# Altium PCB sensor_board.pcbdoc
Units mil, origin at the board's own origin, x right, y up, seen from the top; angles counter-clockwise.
Board outline 4167.27 x 3144 mil, 2 copper layers (Top Layer, Bottom Layer); 44 components, 32 nets, 169 pads, 59 vias.
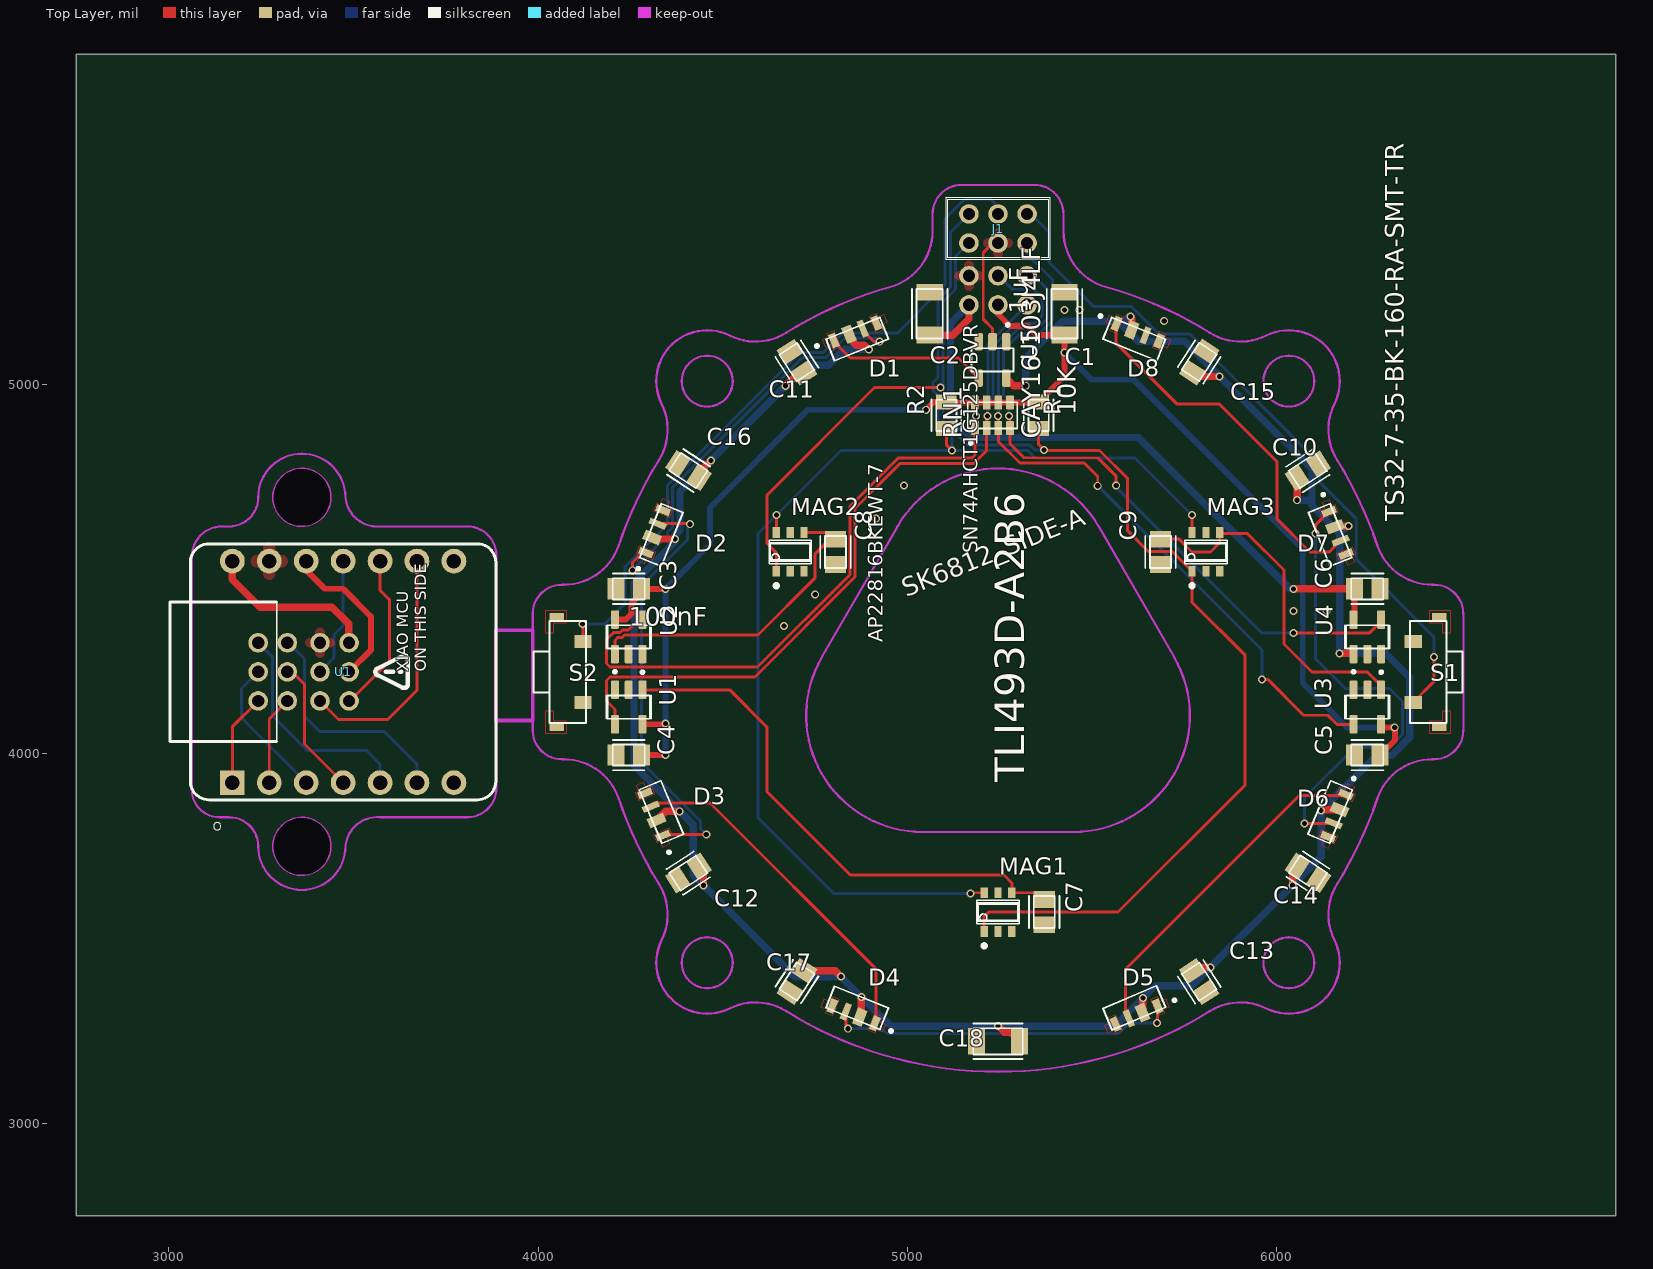
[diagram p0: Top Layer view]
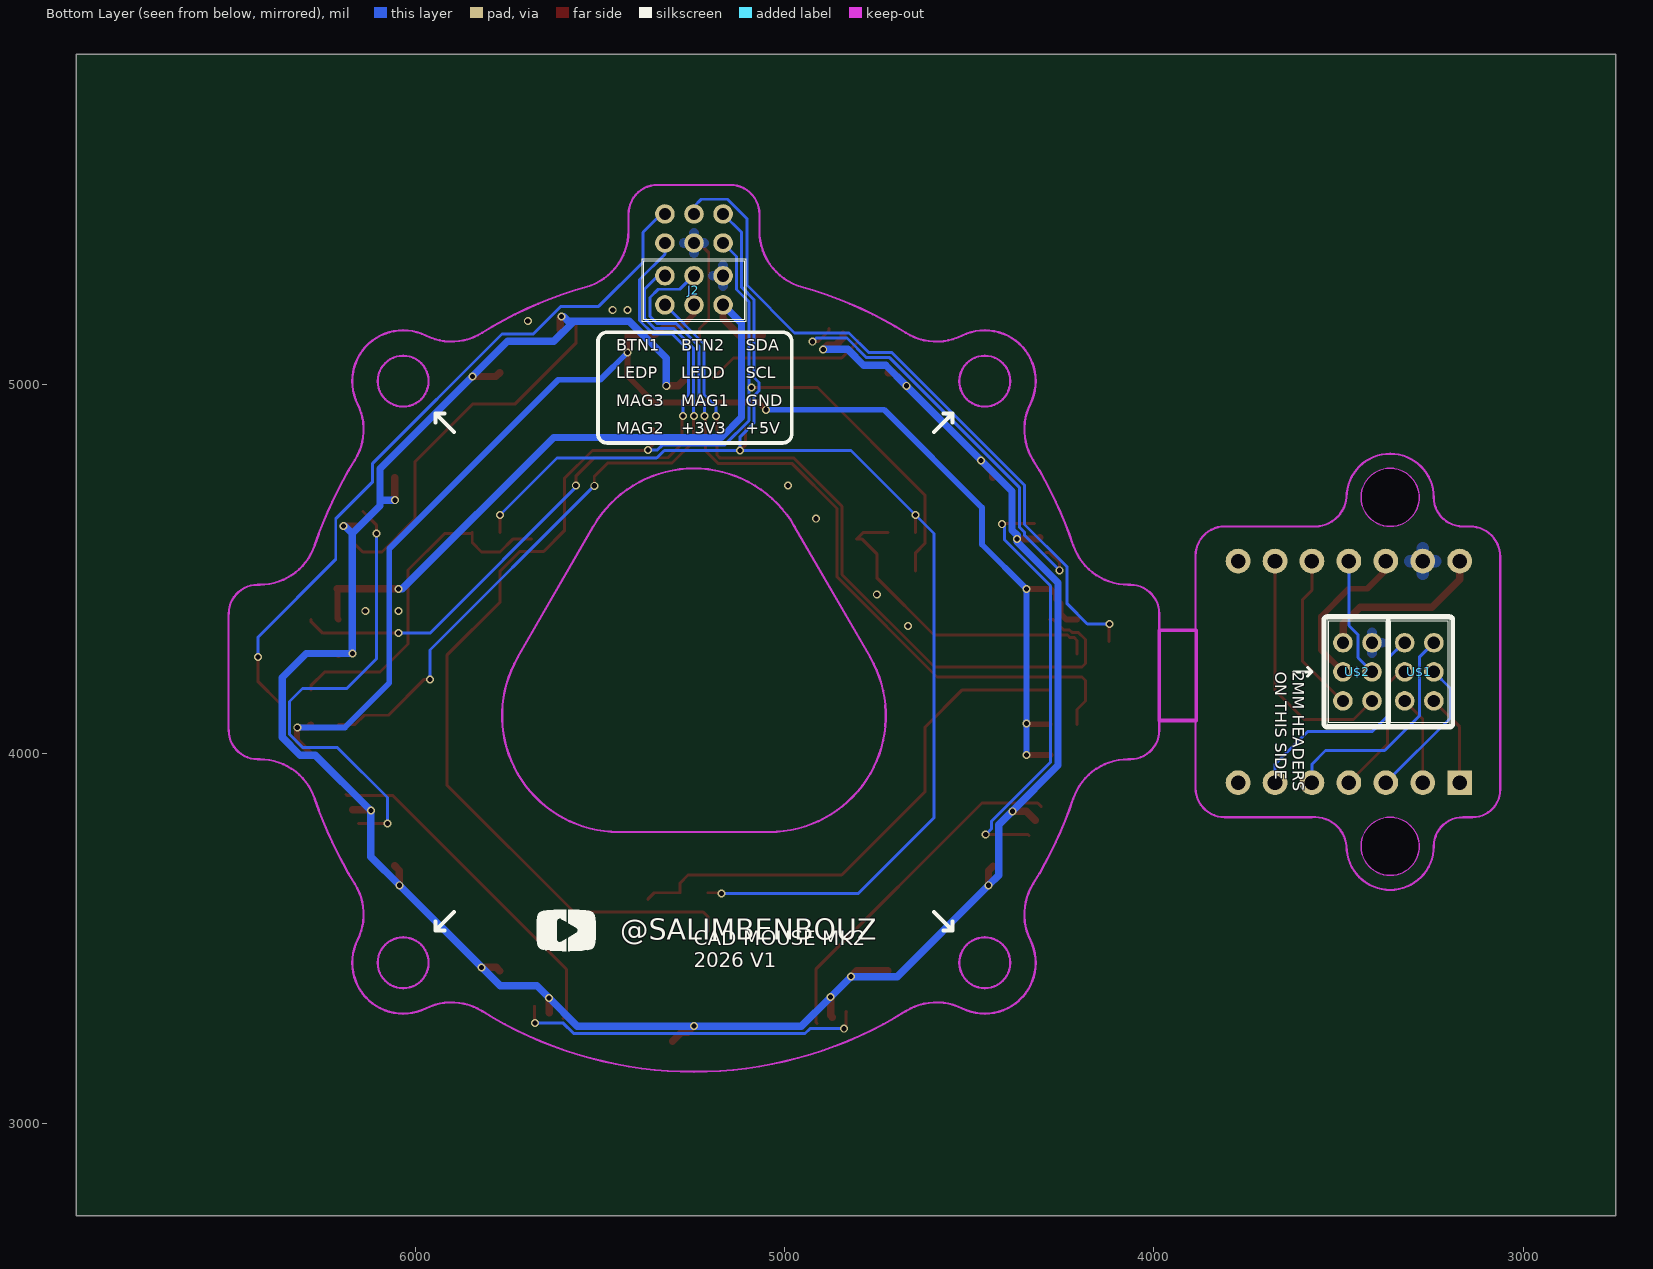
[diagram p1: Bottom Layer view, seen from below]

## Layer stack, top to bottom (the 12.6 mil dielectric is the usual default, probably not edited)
Top Layer: signal copper (thickness not stored)
Dielectric: dielectric 12.6, FR-4, Dk 4.8
Bottom Layer: signal copper (thickness not stored)

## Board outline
6917.27,2750 2750,2750 2750,5894 6917.27,5894
cut-out: 3438.93,3749.95 cw(c3360.19,3749.95) 3281.45,3749.95 cw(c3360.19,3749.95)
cut-out: 3438.93,4694.83 cw(c3360.19,4694.83) 3281.45,4694.83 cw(c3360.19,4694.83)

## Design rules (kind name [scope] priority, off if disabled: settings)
BoardOutlineClearance safeClearance [All] p0: genericclearance=10 ignorepadtopadclearanceinfootprint=FALSE except(0: SMDPad-CutoutEdge THPad-CutoutEdge Via-CutoutEdge Fill-CutoutEdge Arc-SplitContinuation Track-SplitContinuation SMDPad-SplitContinuation THPad-SplitContinuation Via-SplitContinuation Fill-SplitContinuation Poly-SplitContinuation Region-SplitContinuation Text-SplitContinuation; 6: Track-CutoutEdge; 10: Region-CutoutEdge; 11.8: Track-OutlineEdge SMDPad-OutlineEdge THPad-OutlineEdge Via-OutlineEdge Fill-OutlineEdge Region-OutlineEdge Poly-OutlineEdge Text-OutlineEdge)
Clearance safeClearance [(InNet('GND') OR InNet('N$1') OR InNet('N$2') OR InNet('N$4') OR InNet('N$5') OR InNet('N$6') OR InNet('G_5V') OR InNet('5V') OR InNet('SCL') OR InNet('SDA') OR InNet('G_MAG1') OR InNet('G_MAG2') OR InNet('G_MAG3') OR InNet('3V3') OR InNet('BTN_1') OR InNet('BTN_2') OR InNet('LED_DIN') OR InNet('N$3') OR InNet('N$7') OR InNet('~EN_MAG2~') OR InNet('D3') OR InNet('D0') OR InNet('D1') OR InNet('D8') OR InNet('D9') OR InNet('D2') OR InNet('D10') OR InNet('SDA1') OR InNet('SCL1') OR InNet('3V31') OR InNet('5V1') OR InNet('GND1'))] p1: gap=7 ignorepadtopadclearanceinfootprint=FALSE except(0: SMDPad-THPad THPad-THPad THPad-Via SMDPad-Fill THPad-Fill Via-Fill Fill-Fill SMDPad-Region THPad-Region Via-Region Fill-Region SMDPad-Poly THPad-Poly Via-Poly Fill-Poly Region-Poly Poly-Poly SMDPad-Text THPad-Text Via-Text Fill-Text Region-Text Poly-Text Text-Text SMDPad-Hole THPad-Hole Via-Hole Fill-Hole Region-Hole Poly-Hole Text-Hole; 6: Track-Track Track-SMDPad SMDPad-SMDPad Track-THPad Track-Via SMDPad-Via Via-Via Track-Fill Track-Region Track-Poly Track-Text Track-Hole; 10: Region-Region; 11.8: Track-Sheet SMDPad-Sheet THPad-Sheet Via-Sheet Fill-Sheet Region-Sheet Poly-Sheet Text-Sheet Sheet-Hole)
DiffPairsRouting differentialPair [All] p1: maxuncoupledlength=10 minlimit=6 maxlimit=6 mostfreqgap=6 toplayer_minwidth=5 toplayer_prefwidth=10 toplayer_maxwidth=100 bottomlayer_minwidth=5 bottomlayer_prefwidth=10 bottomlayer_maxwidth=100
PasteMaskExpansion Common [All] p1: expansion=0
PlaneConnect innerPlane [All] p1: planeconnectstyle=Relief reliefexpansion=20 reliefentries=4 reliefconductorwidth=10 reliefairgap=10
PolygonConnect CopperRegion [All] p1: connectstyle=Direct reliefentries=4 reliefconductorwidth=10 polygonreliefangle="90 Angle" airgapwidth=50
PolygonConnect CopperRegion1 [All] p1: connectstyle=Direct reliefentries=4 reliefconductorwidth=10 polygonreliefangle="90 Angle" airgapwidth=50
RoutingVias viaSize [All] p1: viastyle="Through Hole" holewidth=11.811 minholewidth=11.811 maxholewidth=78.7402 width=11.811 minwidth=11.811 maxwidth=102.3622
RoutingVias default [All] p1: viastyle="Through Hole" holewidth=0 minholewidth=0 maxholewidth=78.7402 width=0 minwidth=0 maxwidth=102.3622
SolderMaskExpansion Common [All] p1: useseparateexpansions=TRUE expansion=0 expansionbottom=0
Width trackWidth [All] p1: maxlimit=100 minlimit=6 preferedwidth=6
Width default [All] p1: maxlimit=100 minlimit=0 preferedwidth=0

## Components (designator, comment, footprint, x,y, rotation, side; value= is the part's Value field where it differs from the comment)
C1 "1uF" CAPC3216X135 5425.27,5192 r270 top
C2 "1uF" CAPC3216X135 5060.27,5192 r270 top
C3 "100nF" CAPC2012X110 4245.27,4447 r0 top
C4 "100nF" CAPC2012X110 4245.27,3997 r0 top
C5 "100nF" CAPC2012X110 6245.27,3997 r0 top
C6 "100nF" CAPC2012X110 6245.27,4447 r180 top
C7 "100nF" CAPC2012X110 5370.27,3572 r90 top
C8 "100nF" CAPC2012X110 4805.27,4547 r90 top
C9 "100nF" CAPC2012X110 5685.27,4547 r90 top
C10 "100nF" CAPC2012X110 6083.94,4766.64 r213 top
C11 "100nF" CAPC2012X110 4700.63,5060.67 r303 top
C12 "100nF" CAPC2012X110 4406.6,3677.36 r33 top
C13 "100nF" CAPC2012X110 5789.91,3383.33 r123 top
C14 "100nF" CAPC2012X110 6084.36,3678.25 r147 top
C15 "100nF" CAPC2012X110 5790.33,5061.55 r237 top
C16 "100nF" CAPC2012X110 4407.02,4767.52 r327 top
C17 "100nF" CAPC2012X110 4701.05,3384.21 r57 top
C18 "22uF" CAPC3216X135 5245.27,3222 r0 top
D1 "SK6812_SIDE-A" LED_SK6812_SIDE-A 4864.03,5123.25 r22 top
D2 "SK6812_SIDE-A" LED_SK6812_SIDE-A 4333.66,4592.88 r68 top
D3 "SK6812_SIDE-A" LED_SK6812_SIDE-A 4333.66,3842.82 r113 top
D4 "SK6812_SIDE-A" LED_SK6812_SIDE-A 4864.03,3312.45 r158 top
D5 "SK6812_SIDE-A" LED_SK6812_SIDE-A 5614.09,3312.45 r203 top
D6 "SK6812_SIDE-A" LED_SK6812_SIDE-A 6144.46,3842.82 r247 top
D7 "SK6812_SIDE-A" LED_SK6812_SIDE-A 6144.46,4592.88 r292 top
D8 "SK6812_SIDE-A" LED_SK6812_SIDE-A 5614.09,5123.25 r338 top
J1 "NPPN032AFCN-RCCONN3X2_NPPN032AFCN-RC_SUL" CONN3X2_NPPN032AFCN-RC_SUL 5245.27,5422.79 r0 top
J2 "NPPN032AFCN-RCCONN3X2_NPPN032AFCN-RC_SUL" CONN3X2_NPPN032AFCN-RC_SUL 5245.27,5255.46 r0 bottom
MAG1 "TLI493D-A2B6" SOP95P280X110-6N-V 5245.27,3572 r90 top
MAG2 "TLI493D-A2B6" SOP95P280X110-6N-V 4682.35,4547 r90 top
MAG3 "TLI493D-A2B6" SOP95P280X110-6N-V 5808.19,4547 r90 top
R1 "10K" RESC2012X65 5355.27,4917 r90 top
R2 "10K" RESC2012X65 5105.27,4917 r90 top
RN1 "CAY16-103J4LF" RESCAF80P320X160X60-8N 5230.27,4917 r90 top
S1 "TS32-7-35-BK-160-RA-SMT-TR" SW_TS32-7-35-BK-160-RA-SMT-TR 6420.27,4222 r90 top
S2 "TS32-7-35-BK-160-RA-SMT-TR" SW_TS32-7-35-BK-160-RA-SMT-TR 4070.27,4222 r270 top
U1 "AP22816BKEWT-7" SOT95P280X100-5N 4245.27,4127 r270 top
U1 "XIAO-THRUHOLE" XIAO-GENERIC-THRUHOLE-MODULE14P-2.54-21X17.8MM 3472,4222.39 r90 top
U2 "AP22816BKEWT-7" SOT95P280X100-5N 4245.27,4317 r90 top
U3 "AP22816BKEWT-7" SOT95P280X100-5N 6245.27,4127 r270 top
U4 "AP22816BKEWT-7" SOT95P280X100-5N 6245.27,4317 r90 top
U5 "SN74AHCT1G125DBVR" SOT95P280X145-5N 5230.27,5067 r270 top
U$1 "NRPN032PAEN-RC" CONN3X2_NRPN032PAEN-RC 3281.45,4222.39 r90 bottom
U$2 "NRPN032PAEN-RC" CONN3X2_NRPN032PAEN-RC 3448.77,4222.39 r90 bottom

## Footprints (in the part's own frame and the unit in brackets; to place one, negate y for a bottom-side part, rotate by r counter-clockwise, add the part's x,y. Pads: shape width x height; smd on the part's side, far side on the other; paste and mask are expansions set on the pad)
CAPC2012X110 [mil]
  rect 45.85x57.69 smd: 1(-34.46,0) 2(34.46,0)
  silkscreen extent -43,-41 43,41
CAPC3216X135 [mil]
  rect 45.85x71.47 smd: 1(-58.09,0) 2(58.09,0)
  silkscreen extent -67,-48 67,48
CONN3X2_NPPN032AFCN-RC_SUL [mil]
  round 53 hole 33: 1(78.74,39.37) 2(78.74,-39.37) 3(0,39.37) 4(0,-39.37) 5(-78.74,39.37) 6(-78.74,-39.37)
  silkscreen extent -142,-84 142,84
CONN3X2_NRPN032PAEN-RC [mil]
  round 53 hole 33: 1(78.74,39.37) 2(78.74,-39.37) 3(0,39.37) 4(0,-39.37) 5(-78.74,39.37) 6(-78.74,-39.37)
  silkscreen extent -142,-84 142,84
LED_SK6812_SIDE-A [mm]
  rect 0.5x1 smd: 1(-1.525,0.525) 4(1.625,0.525)
  rect 0.7x1.2 smd: 2(-0.4,0.525)
  rect 0.45x1.2 smd: 3(0.625,0.525)
  silkscreen extent -2.85,-0.8 2,0.8
RESC2012X65 [mil]
  rect 40.6x55.91 smd: 1(-36.2,0) 2(36.2,0)
  silkscreen extent -42,-40 42,40
RESCAF80P320X160X60-8N [mm]
  rrect25% 0.97x0.53 smd: 1(-0.875,1.2) 2(-0.875,0.4) 3(-0.875,-0.4) 4(-0.875,-1.2) 5(0.875,-1.2) 6(0.875,-0.4) 7(0.875,0.4) 8(0.875,1.2)
  silkscreen extent -2,-1.7 0.9,1.7
SOP95P280X110-6N-V [mm]
  rect 0.75x0.5 smd: 1(-1.325,0.95) 2(-1.325,0) 3(-1.325,-0.95) 4(1.325,-0.95) 5(1.325,0) 6(1.325,0.95)
  silkscreen extent -2.45,-1.45 0.8,1.45
SOT95P280X100-5N [mm]
  rrect25% 1.26x0.55 smd: 1(-1.185,0.95) 2(-1.185,0) 3(-1.185,-0.95) 4(1.185,-0.95) 5(1.185,0.95)
  silkscreen extent -2.5,-1.55 0.8,1.55
SOT95P280X145-5N [mm]
  rrect50% 1.21x0.59 smd: 1(-1.255,0.95) 2(-1.255,0) 3(-1.255,-0.95) 4(1.255,-0.95) 5(1.255,0.95)
  silkscreen extent -2.51,-1.45 0.8,1.45
SW_TS32-7-35-BK-160-RA-SMT-TR [mm]
  rect 0.9x1.2 smd: 1(-2.1,1.3) 2(2.1,1.3)
  rect 0.5x1 smd: SH1(-3.8,-0.5) SH2(3.8,-0.5)
  silkscreen extent -3.5,-2.1 3.5,1.5
XIAO-GENERIC-THRUHOLE-MODULE14P-2.54-21X17.8MM [mm]
  rect 1.7x1.7 hole 1: 1(-7.62,7.62)
  round 1.7 hole 1: 2(-7.62,5.08) 3(-7.62,2.54) 4(-7.62,0) 5(-7.62,-2.54) 6(-7.62,-5.08) 7(-7.62,-7.62) 8(7.62,-7.62) 9(7.62,-5.08) 10(7.62,-2.54) 11(7.62,0) 12(7.62,2.54) 13(7.62,5.08) 14(7.62,7.62)
  silkscreen extent -10.87,-10.5 8.8,11.92

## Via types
v1: diameter 21.65, hole 13.78, Top Layer to Bottom Layer, 59 vias

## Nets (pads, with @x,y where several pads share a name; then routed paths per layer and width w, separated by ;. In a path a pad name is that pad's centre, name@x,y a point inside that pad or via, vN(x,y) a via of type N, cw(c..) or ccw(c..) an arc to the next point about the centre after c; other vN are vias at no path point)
3V3: C1.2 C3.2 C4.2 C5.2 J1.6 J2.3 J2.4 R1.2 R2.2 RN1.2 RN1.4 RN1.5 RN1.6 RN1.7 RN1.8 U1.4@4207.87,4080.35 U1.5@4282.67,4080.35 U2.5 U3.5 U4.4 | length 8244
  Top Layer w8: U1.4@4207.87,4080.35 4207.87,4120.47 4185.27,4143.07 4185.27,4199.24 4194.48,4208.46 4586.9,4208.46 4858.11,4479.67 4858.11,4664.84 4980.27,4787 5180.07,4787 5214.52,4821.45 RN1.2 5214.52,4913.29 v1(5216.76,4915.53) ; v1(5275.27,4915.53) 5277.51,4913.28 RN1.4 5277.51,4839.76 5315.27,4802 5515.27,4802 5565.27,4752 v1(5565.27,4727) ; v1(6045.27,4327) 6250.27,4327 6282.67,4359.4 U4.4
  Top Layer w15.98: R1.2 5425.27,5023.2 v1(5425.27,5087)
  Top Layer w16: U2.5 4236.47,4363.65 4252.84,4380.03 4252.84,4407.67 4264.73,4419.56 4264.73,4432 C3.2 v1(4345.27,4447) ; C4.2 v1(4345.27,3997) ; U1.5@4282.67,4080.35 4343.62,4080.35 v1(4345.27,4082) ; v1(5050.27,4932) 5071.47,4953.2 R2.2 5107.02,4951.45 RN1.8 RN1.7 RN1.6 RN1.5 5353.52,4951.45 R1.2 ; J2.3 5245.27,5191.09 5277.45,5158.91 5325.27,5158.91 5350.27,5133.91 C1.2 v1(5425.27,5087) ; C5.2 6320.27,4037.54 6320.27,4072 6291.02,4072 U3.5
  Bottom Layer w8: v1(5216.76,4915.53) 5216.76,4952.22 5232.27,4967.73 5232.27,5104.6 5293.26,5165.59 5344.93,5165.59 5364.51,5185.18 5364.51,5235.84 5342.01,5258.33 5283.89,5258.33 5247.39,5294.83 J2.4 ; v1(5275.27,4915.53) 5275.27,4957 5260.27,4972 5260.27,5093 5304.86,5137.59 5356.53,5137.59 5392.51,5173.58 5392.51,5284.76 5324.01,5353.26 5324.01,5383.42 ; v1(5565.27,4727) 5565.27,4722 5960.27,4327 v1(6045.27,4327)
  Bottom Layer w16: v1(4345.27,3997) v1(4345.27,4082) v1(4345.27,4447) 4465.27,4567 4465.27,4667 4730.27,4932 v1(5050.27,4932) ; v1(5425.27,5087) 5499.02,5013.25 5612.77,5013.25 6070.27,4555.75 6070.27,4192 6190.27,4072 v1(6319.44,4072)
3V31: U1.12 U$2.3 | length 426.2
  Top Layer w16: U1.12 3372,4497.39 3422,4447.39 3472,4447.39 3547,4372.39 3547,4281.25 U$2.3
5V: C2.2 C6.2 J2.5 U4.5 | length 1859.1
  Top Layer w16: U4.5 6210.8,4366.59 C6.2
  Top Layer w20: C2.2 5122.18,5133.91 5166.53,5178.26 J2.5 ; v1(6045.27,4447) C6.2
  Bottom Layer w20: J2.5 5116.53,5166.09 5116.53,4911.33 5170.86,4857 5625.27,4857 6035.27,4447 v1(6045.27,4447)
5V1: U1.14 U$2.1 | length 466.4
  Top Layer w20: U1.14 3172,4472.39 3247,4397.39 3442,4397.39 3487,4352.39 3487,4302.28 U$2.1
BTN_1: J1.5 S1.1 | length 1917.7
  Top Layer w8: S1.1 6425.27,4195.5 v1(6425.27,4262)
  Bottom Layer w8: 5324.01,5462.16 5334.01,5462.16 5383.62,5412.54 5383.62,5331.64 5503.26,5212 5605.27,5212 5680.27,5137 5765.27,5137 6115.27,4787 6115.27,4737 6215.27,4637 6215.27,4527 6425.27,4317 v1(6425.27,4262)
BTN_2: J1.3 S2.1 | length 1903.1
  Top Layer w8: v1(4120.27,4352) 4121.45,4350.82 S2.1
  Bottom Layer w8: v1(4120.27,4352) 4180.27,4352 4234.86,4406.59 4234.86,4506.04 4350.27,4621.45 4350.27,4727.76 4709.5,5087 4772.19,5087 4825.36,5140.17 4972.72,5140.17 5102.03,5269.48 5102.03,5449.28 5154.75,5502 5225.27,5502 5245.27,5482 J1.3
D0: U1.1@3172,3922.39 U$1.6 | length 250.3
  Top Layer w8: U1.1@3172,3922.39 3172,4073.57 U$1.6
D1: U1.2@3272,3922.39 U$1.5 | length 241.5
  Top Layer w8: U1.2@3272,3922.39 3272,4094.83 U$1.5
D2: U1.3@3372,3922.39 U$1.4 | length 391.1
  Bottom Layer w8: U$1.4@3242,4222.39 3197,4177.39 3197,4097.39 U1.3@3372,3922.39
D3: U1.4@3472,3922.39 U$1.3 | length 370.2
  Top Layer w8: U$1.3 3333.7,4222.39 3367.32,4188.77 3367.32,4027.07 U1.4@3472,3922.39
D8: U1.9 U$2.6 | length 666.1
  Top Layer w8: U$2.6 3459.66,4093.39 3593,4093.39 3672,4172.39 U1.9
D9: U1.10 U$2.5 | length 435.4
  Top Layer w8: U$2.5 3490.14,4143.65 3597,4250.51 3597,4418.39 3572,4443.39 U1.10
D10: U1.11 U$2.4 | length 325.9
  Bottom Layer w8: U$2.4 3447.64,4260.63 3447.64,4323.04 3472,4347.39 U1.11
G_5V: C10.2 C11.2 C12.2 C13.2 C14.2 C15.2 C16.2 C17.2 C18.2 D1.2 D2.2 D3.2 D4.2 D5.2 D6.2 D7.2 D8.2 U4.1 U5.5 | length 7558.9
  Top Layer w20: D2.2 4312.62,4582 v1(4370.27,4582) ; D3.2 4345.31,3844.77 v1(4383.04,3844.77) ; C12.2 4447.77,3683.87 v1(4447.77,3644.5) ; C16.2 4435.92,4762.65 v1(4467.77,4794.5) ; v1(4670.27,4997) 4705.03,5031.77 C11.2 ; C17.2 4804.15,3413.12 v1(4820.27,3397) ; D1.2 4841.69,5126.52 4861.21,5107 4883.62,5107 v1(4895.27,5095.35) ; D4.2 4875.27,3291.76 v1(4875.27,3342) ; v1(5245.27,3263.66) 5261.93,3247 5278.36,3247 C18.2 ; U5.5 5288.26,4997 v1(5320.27,4997) ; v1(5603.46,5184.36) 5607.23,5180.58 D8.2 ; D5.2 5636.66,3338.39 v1(5637.77,3339.5) ; C13.2 5780.9,3422 v1(5820.27,3422) ; C15.2 5782.21,5022 v1(5845.27,5022) ; v1(6042.77,3644.5) 6042.77,3684.33 C14.2 ; C10.2 6055.03,4687.23 v1(6055.27,4687) ; v1(6120.27,3847) 6122.51,3849.24 D6.2 ; D7.2 6159.5,4617 v1(6194.44,4617) ; v1(6170.27,4272) 6206.21,4272 U4.1
  Bottom Layer w20: v1(4383.04,3844.77) v1@4383.63,3845.36 ; v1(4895.27,5095.35) 4828.62,5095.35 4785.27,5052 4725.27,5052 v1(4670.27,4997) v1(4467.77,4794.5) 4384.27,4711 4384.27,4606 4370.27,4592 v1(4370.27,4582) 4370.27,4574.06 4259.74,4463.53 4259.74,3969.25 v1@4383.63,3845.36 ; v1(5245.27,3263.66) v1@5245.27,3262.83 ; v1(5320.27,4997) 5320.27,5072 5420.27,5172 5570.27,5172 ; v1(5603.46,5184.36) 5597.63,5184.36 5585.27,5172 5570.27,5172 ; v1(6055.27,4687) 6095.27,4687 ; v1(6194.44,4617) 6190.27,4617 6170.27,4597 ; v1@4383.63,3845.36 4420.27,3808.72 4420.27,3672 v1(4447.77,3644.5) 4695.27,3397 v1(4820.27,3397) v1(4875.27,3342) 4954.44,3262.83 v1@5245.27,3262.83 ; v1@5245.27,3262.83 5561.1,3262.83 v1(5637.77,3339.5) 5670.27,3372 5770.27,3372 v1(5820.27,3422) v1(6042.77,3644.5) 6120.27,3722 v1(6120.27,3847) 6270.27,3997 6312.18,3997 6360.27,4045.09 6360.27,4207 6295.27,4272 v1(6170.27,4272) 6170.27,4597 ; 5570.27,5172 5625.27,5117 5750.27,5117 v1(5845.27,5022) 6095.27,4772 6095.27,4687 ; 6095.27,4687 6095.27,4672 6170.27,4597
G_MAG1: C7.2 MAG1.4 U1.1@4282.67,4173.65 | length 1440.5
  Top Layer w8: U1.1@4282.67,4173.65 4518.62,4173.65 4620.27,4072 4620.27,3897 4845.27,3672 5261.18,3672 5282.67,3650.51 MAG1.4 5352.57,3624.17 C7.2
G_MAG2: C8.2 MAG2.4 U2.1 | length 878.9
  Top Layer w8: U2.1 4207.87,4307.45 4215.27,4314.85 4227.05,4314.85 4234.2,4322 4595.27,4322 4750.27,4477 4750.27,4542 4789.73,4581.46 C8.2 4787.57,4599.17 MAG2.4
G_MAG3: C9.2 MAG3.4 U3.1 | length 948.8
  Top Layer w8: C9.2 5735.8,4581.46 5770.27,4547 5820.27,4547 5845.59,4572.32 MAG3.4 5847.75,4597 5920.27,4597 6019.44,4497.83 6019.44,4297.83 6095.27,4222 6245.27,4222 6282.67,4184.6 U3.1
GND: C1.1 C2.1 C3.1 C4.1 C5.1 C6.1 C7.1 C8.1 C9.1 C10.1 C11.1 C12.1 C13.1 C14.1 C15.1 C16.1 C17.1 C18.1 D1.4 D2.4 D3.4 D4.4 D5.4 D6.4 D8.4 J1.4 J2.6 MAG1.2 MAG1.3 MAG1.5 MAG2.2 MAG2.3 MAG2.5 MAG3.2 MAG3.3 MAG3.5 S1.2 S2.2 U1.2@4245.27,4173.65 U2.2 U3.2 U4.2 U5.1 U5.2 U5.3 | length 301.9
  Top Layer w8: U5.2 5230.27,5152 5205.27,5177 5205.27,5357 5231.69,5383.42 J1.4
  other v1: 4665.27,4347 6045.27,4387 6135.27,4387 4750.27,4432 4915.27,4637 4990.27,4727
GND1: U1.13 U$2.2
LED_DIN: D1.1 U5.4 | length 436.6
  Top Layer w8: D1.1 4800.62,5116.65 4845.27,5072 5138.46,5072 U5.4
N$1: D1.3 D2.1 | length 1132.8
  Top Layer w8: v1(4255.68,4497.41) 4255.68,4518.63 4282,4544.96 D2.1 ; D1.3 4879.1,5146.53 4909.46,5116.17 v1(4924.46,5116.17)
  Bottom Layer w8: v1(4255.68,4497.41) 4350.27,4592 4350.27,4600.28 4364.27,4614.28 4364.27,4721.97 4715.3,5073 4777.98,5073 4831.16,5126.17 4914.46,5126.17 v1(4924.46,5116.17)
N$2: D2.3 D3.1 | length 1173.3
  Top Layer w8: D2.3 4408.83,4623.44 4410.27,4622 v1(4411.1,4622) ; D3.1 4340.61,3782 v1(4455.27,3782)
  Bottom Layer w8: v1(4411.1,4622) 4404.27,4615.17 4404.27,4579.78 4279.74,4455.24 4279.74,3977.53 4440.27,3817 4440.27,3797 v1(4455.27,3782)
N$3: D6.3 D7.1 | length 1270
  Top Layer w8: v1(6075.27,3812) 6075.37,3812.1 D6.3 ; v1(6105.27,4597) 6105.27,4620.42 D7.1
  Bottom Layer w8: v1(6075.27,3812) 6075.27,3882 6210.27,4017 6303.9,4017 6340.27,4053.37 6340.27,4142 6305.27,4177 6185.27,4177 6105.27,4257 v1(6105.27,4597)
N$4: D3.3 D4.1 | length 948.2
  Top Layer w8: D3.3 4314.62,3867 4465.27,3867 4915.27,3417 4915.27,3274.11 D4.1
N$5: D4.3 D5.1 | length 948.7
  Top Layer w8: D4.3 4832.84,3301.87 4833.44,3301.26 4833.44,3261.97 v1(4839.34,3256.07) ; v1(5675.27,3272) 5677.43,3274.16 D5.1
  Bottom Layer w8: v1(4839.34,3256.07) 4931.19,3256.07 4944.44,3242.83 5571.1,3242.83 5600.27,3272 v1(5675.27,3272)
N$6: D5.3 D6.1 | length 929.6
  Top Layer w8: D5.3 5590.27,3293.06 5590.27,3417 6060.25,3886.98 6183.92,3886.98 D6.1
N$7: D7.3 D8.1 | length 998.4
  Top Layer w8: D8.1 5565.27,5164.01 5565.27,5112 5730.27,4947 5780.27,4947 5845.27,4947 6000.27,4792 6000.27,4637 6090.27,4547 6142.04,4547 D7.3
SCL: J1.2 MAG1.1 MAG2.1 MAG3.1 R1.1 | length 3846.2
  Top Layer w8: MAG2.1 4644.95,4544.83 4620.27,4569.52 4620.27,4701.45 4910.81,4992 v1(5089.7,4992) ; MAG1.1 5207.87,3559.6 5220.27,3572 5570.27,3572 5914.43,3916.16 5914.43,4267 5770.78,4410.64 MAG3.1 5717.08,4548.54 5652.28,4548.54 5596.42,4604.4 5596.42,4745.84 5520.27,4822 5370.27,4822 v1(5370.27,4822.83) 5355.27,4837.83 R1.1
  Bottom Layer w8: v1(5089.7,4992) v1@5096.53,4992 ; 5166.53,5383.42 5130.03,5346.92 5130.03,5257.88 5096.53,5224.38 v1@5096.53,4992 ; v1(5370.27,4822.83) 5344.44,4822.83 5331.27,4836 5162.98,4836 5096.53,4902.46 v1@5096.53,4992
SCL1: U1.6 U$1.1 | length 628.4
  Bottom Layer w8: U$1.1 3323.7,4301.13 3367.32,4257.51 3367.32,4102.07 3408,4061.39 3583,4061.39 3672,3972.39 U1.6
SDA: J1.1 MAG1.6 MAG2.6 MAG3.6 R2.1 | length 3672
  Top Layer w8: MAG2.6 4645.27,4599.48 v1(4645.27,4647) ; R2.1 5105.27,4837 v1(5120.27,4822) ; v1(5170.27,3622) 5172.43,3624.17 MAG1.6 ; v1(5770.27,4647) 5770.78,4646.48 MAG3.6
  Bottom Layer w8: 5166.53,5462.16 5116.03,5411.66 5116.03,5263.68 5082.53,5230.18 5082.53,5019.26 5068.88,5005.61 5068.88,4983.37 5082.53,4969.72 5082.53,4896.66 5120.27,4858.92 v1(5120.27,4822) ; v1(5170.27,3622) 4800.27,3622 4595.27,3827 4595.27,4597 v1(4645.27,4647) 4820.27,4822 v1(5120.27,4822) ; v1(5770.27,4647) 5616.1,4801.17 5346.3,4801.17 5325.47,4822 v1(5120.27,4822)
SDA1: U1.5@3572,3922.39 U$1.2 | length 609.1
  Bottom Layer w8: U$1.2 3281.32,4261.89 3281.32,4103.07 3375,4009.39 3535,4009.39 3572,3972.39 U1.5@3572,3922.39
~EN_MAG2~: J2.1 J2.2 RN1.1 RN1.3 U2.4 U3.4 | length 3905.1
  Top Layer w8: U2.4 4271.92,4363.65 4244.27,4336 4228.4,4336 4221.25,4328.85 4204.47,4328.85 4185.27,4309.65 4185.27,4244.76 4194.48,4235.54 4594.19,4235.54 4844.11,4485.47 4844.11,4670.64 4974.47,4801 5174.27,4801 5183.02,4809.76 RN1.1 5183.02,4913.28 v1(5185.27,4915.53) ; v1(5245.27,4915.53) 5246.02,4914.78 RN1.3 5246.02,4846.25 5304.73,4787.54 5478.9,4787.54 5515.27,4751.17 v1(5515.27,4726.17) ; v1(5960.27,4202) 5975.47,4202 6072.62,4104.85 6138.36,4104.85 6162.87,4080.35 U3.4
  Bottom Layer w8: v1(5185.27,4915.53) 5185.27,4940.53 5218.27,4973.53 5218.27,5110.4 J2.1 ; v1(5245.27,4915.53) 5245.27,4920.53 5246.27,4921.53 5246.27,5098.8 5299.06,5151.59 5350.73,5151.59 5378.51,5179.38 5378.51,5258.76 5342.43,5294.83 J2.2 ; v1(5515.27,4726.17) 5960.27,4281.17 v1(5960.27,4202)
pads on no net: D7.4 D8.3 S1.SH1 S1.SH2 S2.SH1 S2.SH2 U1.3@4207.87,4173.65 U1.7 U1.8 U2.3 U3.3 U4.3
copper on no net:
  other v1: 5695.27,5172 5425.27,5202 5465.27,5202

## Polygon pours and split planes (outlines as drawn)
GND on Bottom Layer (solid, remove dead copper, pour order 4): 3848.27,3000 6667.27,3000 6667.27,5644 3848.27,5644
GND on Top Layer (solid, remove dead copper, pour order 0): 3873.27,3025 6642.27,3025 6642.27,5619 3873.27,5619
GND1 on Top Layer (solid, remove dead copper, pour order 54): 3944,3600.39 3944,4844.39 3025,4844.39 3025,3600.39
GND1 on Bottom Layer (solid, remove dead copper, pour order 10): 3969,3575.39 3969,4869.39 3000,4869.39 3000,3575.39
no net on Top Layer (solid, remove dead copper, pour order 2): 4945.02,5169.78 4936.91,5189.85 4920.59,5183.26 4920.44,5183.32 4916.8,5192.34 4896.72,5184.23 4914.42,5140.43 4934.5,5148.54 4928.64,5163.03 4928.7,5163.18
no net on Top Layer (solid, remove dead copper, pour order 2): 4793.43,5108.53 4793.58,5108.46 4799.43,5093.97 4819.51,5102.08 4801.81,5145.89 4781.74,5137.77 4785.38,5128.76 4785.32,5128.61 4769,5122.01 4777.11,5101.93
no net on Top Layer (solid, remove dead copper, pour order 2): 6471.45,4115.7 6447.83,4115.7 6447.83,4088.26 6447.71,4088.14 6412.39,4088.14 6412.39,4056.65 6471.45,4056.65
no net on Top Layer (solid, remove dead copper, pour order 2): 6412.39,4355.86 6447.71,4355.86 6447.83,4355.74 6447.83,4328.3 6471.45,4328.3 6471.45,4387.35 6412.39,4387.35
no net on Top Layer (solid, remove dead copper, pour order 2): 4356.45,4683.46 4336.38,4691.57 4329.78,4675.25 4329.63,4675.18 4320.61,4678.83 4312.5,4658.75 4356.31,4641.05 4364.42,4661.13 4349.92,4666.99 4349.86,4667.14
no net on Top Layer (solid, remove dead copper, pour order 2): 4295.2,4531.86 4295.36,4531.92 4309.85,4526.07 4317.96,4546.15 4274.16,4563.84 4266.05,4543.77 4275.06,4540.12 4275.13,4539.97 4268.53,4523.65 4288.61,4515.54
no net on Top Layer (solid, remove dead copper, pour order 2): 4285.73,3922.99 4265.8,3914.53 4272.68,3898.33 4272.61,3898.18 4263.66,3894.37 4272.12,3874.44 4315.61,3892.9 4307.15,3912.83 4292.76,3906.73 4292.61,3906.79
no net on Top Layer (solid, remove dead copper, pour order 2): 4349.61,3772.49 4349.68,3772.64 4364.07,3778.75 4355.61,3798.68 4312.12,3780.22 4320.58,3760.29 4329.53,3764.09 4329.68,3764.03 4336.56,3747.82 4356.49,3756.28
no net on Top Layer (solid, remove dead copper, pour order 2): 4773.46,3335.24 4765.35,3315.17 4781.67,3308.57 4781.73,3308.42 4778.08,3299.41 4798.16,3291.29 4815.86,3335.1 4795.78,3343.21 4789.93,3328.71 4789.78,3328.65
no net on Top Layer (solid, remove dead copper, pour order 2): 4925.05,3274 4924.99,3274.15 4930.85,3288.64 4910.77,3296.75 4893.07,3252.95 4913.15,3244.84 4916.79,3253.86 4916.94,3253.92 4933.26,3247.33 4941.37,3267.4
no net on Top Layer (solid, remove dead copper, pour order 2): 5533.92,3264.52 5542.38,3244.59 5558.59,3251.47 5558.74,3251.41 5562.54,3242.45 5582.47,3250.91 5564.01,3294.4 5544.08,3285.94 5550.19,3271.55 5550.13,3271.4
no net on Top Layer (solid, remove dead copper, pour order 2): 5684.43,3328.41 5684.28,3328.47 5678.17,3342.86 5658.24,3334.4 5676.7,3290.91 5696.63,3299.37 5692.83,3308.32 5692.89,3308.47 5709.09,3315.35 5700.63,3335.28
no net on Top Layer (solid, remove dead copper, pour order 2): 6120.09,3752.66 6140.02,3744.2 6146.9,3760.4 6147.05,3760.46 6156.01,3756.66 6164.47,3776.59 6120.98,3795.05 6112.52,3775.12 6126.91,3769.01 6126.97,3768.86
no net on Top Layer (solid, remove dead copper, pour order 2): 6183.98,3903.16 6183.83,3903.1 6169.44,3909.21 6160.97,3889.28 6204.46,3870.82 6212.92,3890.75 6203.97,3894.55 6203.91,3894.7 6210.79,3910.9 6190.85,3919.37
no net on Top Layer (solid, remove dead copper, pour order 2): 6190.99,4511.89 6211.06,4520 6204.47,4536.32 6204.53,4536.47 6213.55,4540.12 6205.44,4560.19 6161.64,4542.49 6169.75,4522.42 6184.24,4528.27 6184.39,4528.21
no net on Top Layer (solid, remove dead copper, pour order 2): 6129.74,4663.49 6129.67,4663.34 6115.18,4657.48 6123.29,4637.4 6167.09,4655.1 6158.98,4675.18 6149.96,4671.53 6149.81,4671.6 6143.22,4687.92 6123.14,4679.81
no net on Top Layer (solid, remove dead copper, pour order 2): 5704.67,5100.46 5712.78,5120.54 5696.46,5127.13 5696.39,5127.28 5700.04,5136.3 5679.96,5144.41 5662.26,5100.61 5682.34,5092.5 5688.2,5106.99 5688.35,5107.05
no net on Top Layer (solid, remove dead copper, pour order 2): 5553.07,5161.71 5553.13,5161.56 5547.28,5147.06 5567.35,5138.95 5585.05,5182.76 5564.98,5190.87 5561.33,5181.85 5561.18,5181.79 5544.86,5188.38 5536.75,5168.3
no net on Top Layer (solid, remove dead copper, pour order 2): 4019.09,4328.3 4042.71,4328.3 4042.71,4355.74 4042.82,4355.86 4078.14,4355.86 4078.14,4387.35 4019.09,4387.35
no net on Top Layer (solid, remove dead copper, pour order 2): 4078.14,4088.14 4042.82,4088.14 4042.71,4088.26 4042.71,4115.7 4019.09,4115.7 4019.09,4056.65 4078.14,4056.65

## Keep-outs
Board Outline Layer:
  circle w6: c6032.67,5009.4 r68.9
  circle w6: c4457.87,5009.4 r68.9
  circle w6: c4457.87,3434.6 r68.9
  circle w6: c6032.67,3434.6 r68.9
  circle w1: c3360.19,3749.95 r78.74
  region: 3438.93,3749.95 cw(c3360.19,3749.95) 3281.45,3749.95 cw(c3360.19,3749.95)
  circle w1: c3360.19,4694.83 r78.74
  region: 3438.93,4694.83 cw(c3360.19,4694.83) 3281.45,4694.83 cw(c3360.19,4694.83)
  lines w6: 6505.11,4064.52 cw(c6426.37,4064.52) 6426.37,3985.78 6421.27,3985.78 ccw(c6421.27,3828.3) 6271.94,3878.29 cw(c5245.27,4222) 6163.77,3648.82 ccw(c6297.37,3565.44) 6156.2,3495.66 cw(c6032.67,3434.6) 5971.61,3311.07 ccw(c5901.83,3169.9) 5818.45,3303.5 cw(c5245.27,4222) 4672.08,3303.5 ccw(c4588.71,3169.9) 4518.93,3311.07 cw(c4457.87,3434.6) 4334.34,3495.66 ccw(c4193.16,3565.44) 4326.77,3648.82 cw(c5245.27,4222) 4218.6,3878.29 ccw(c4069.26,3828.3) 4069.26,3985.78 4064.17,3985.78 cw(c4064.17,4064.52) 3985.43,4064.52 3985.43,4379.48 cw(c4064.17,4379.48) 4064.17,4458.22 4069.26,4458.22 ccw(c4069.26,4615.7) 4218.6,4565.71 cw(c5245.27,4222) 4326.76,4795.18 ccw(c4193.16,4878.56) 4334.34,4948.34 cw(c4457.87,5009.4) 4518.93,5132.93 ccw(c4588.71,5274.1) 4672.08,5140.5 cw(c5245.27,4222) 4953.12,5264.51 ccw(c4910.62,5416.15) 5068.1,5416.15 5068.1,5462.16 cw(c5146.84,5462.16) 5146.84,5540.9 5343.69,5540.9 cw(c5343.69,5462.16) 5422.43,5462.16 5422.43,5416.15 ccw(c5579.91,5416.15) 5537.42,5264.52 cw(c5245.27,4222) 5818.45,5140.5 ccw(c5901.83,5274.1) 5971.61,5132.93 cw(c6032.67,5009.4) 6156.2,4948.34 ccw(c6297.37,4878.56) 6163.77,4795.18 cw(c5245.27,4222) 6271.94,4565.71 ccw(c6421.27,4615.7) 6421.27,4458.22 6426.37,4458.22 cw(c6426.37,4379.48) 6505.11,4379.48 ; 6505.5,4065.31 6505.5,4380.27 ; 3062,3903.65 3062,4533.57 cw(c3144.52,4533.57) 3144.52,4616.09 3163.34,4616.09 ccw(c3163.34,4694.83) 3242.08,4694.83 cw(c3360.19,4694.83) 3478.3,4694.83 ccw(c3564.54,4702.33) 3572.04,4616.09 3808.26,4616.09 cw(c3808.26,4537.35) 3887,4537.35 3887,3907.43 cw(c3808.26,3907.43) 3808.26,3828.69 3572.04,3828.69 ccw(c3564.54,3742.45) 3478.3,3749.95 cw(c3360.19,3749.95) 3242.08,3749.95 ccw(c3163.34,3749.95) 3163.34,3828.69 3136.96,3828.69 cw(c3136.96,3903.65) 3062,3903.65 ; 4767.93,4261.37 ccw(c5040.7,4103.89) 5040.7,3788.93 5449.84,3788.93 ccw(c5449.84,4103.89) 5722.61,4261.37 5518.03,4615.7 ccw(c5245.27,4458.22) 4972.5,4615.7 4767.93,4261.37
  lines w10: 3885.39,4090.72 3985.43,4090.72 3985.43,4335.2 3885.39,4335.2 3885.39,4090.72

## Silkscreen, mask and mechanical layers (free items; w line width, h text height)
Top Silkscreen Layer:
  lines w12: 3588,4222.39 3608,4222.39 ; 3625.51,4222.39 3629,4222.39 ; 3564.89,4213.45 3632.53,4179.63 ccw(c3637,4188.57) 3647,4188.57 3647,4256.21 ccw(c3637,4256.21) 3632.53,4265.16 3564.89,4231.34 ccw(c3569.36,4222.39) 3564.89,4213.45
  text "XIAO MCU / ON THIS SIDE" at 3697,4222.39 h32 r90
Bottom Silkscreen Layer:
  drawing of 36 lines, arcs and shapes, not listed
  text "SDA" at 5105.27,5092 h32
  text "BTN2" at 5280.27,5092 h32
  text "BTN1" at 5455.27,5092 h32
  text "SCL" at 5105.27,5017 h32
  text "LEDD" at 5280.27,5017 h32
  text "LEDP" at 5455.27,5017 h32
  text "GND" at 5105.27,4942 h32
  text "MAG1" at 5280.27,4942 h32
  text "MAG3" at 5455.27,4942 h32
  text "+5V" at 5105.27,4867 h32
  text "+3V3" at 5280.27,4867 h32
  text "MAG2" at 5455.27,4867 h32
  text "2MM HEADERS / ON THIS SIDE" at 3672,4222.39 h32 r90
  text "@SALIMBENBOUZ" at 5445.27,3497 h56
  text "CAD MOUSE MK2  / 2026 V1" at 5245.27,3422 h40
Mechanical Layer:
  circle w1: c3360.19,3749.95 r78.74
  circle w1: c3360.19,4694.83 r78.74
